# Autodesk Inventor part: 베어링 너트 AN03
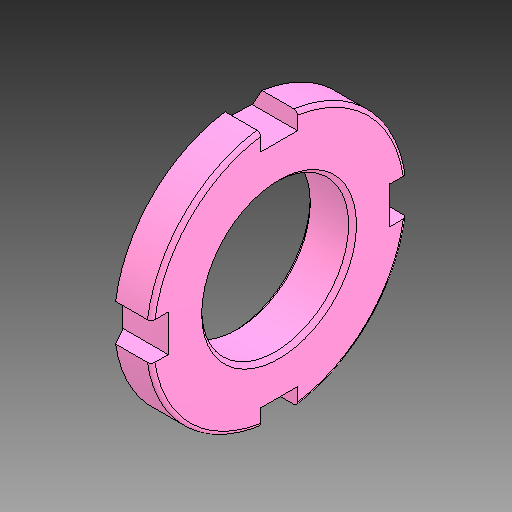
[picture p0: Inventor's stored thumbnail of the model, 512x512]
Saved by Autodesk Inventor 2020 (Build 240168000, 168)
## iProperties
Created: 2025-03
Part Number: 베어링 너트 AN03
Material: 강철, 연강
Description: 홈붙이 둥근 너트
Document SubType Name: Modeling
Designer: CA01
Density: 7.85 g/cm^3
Appearance: 기본값
Author: jhkim
Sending System: Autodesk Inventor 2025
Preprocessor: ST-DEVELOPER v20
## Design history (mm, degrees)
feature "Solid1"
node "솔리드1"
